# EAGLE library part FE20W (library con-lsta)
FEMALE HEADER
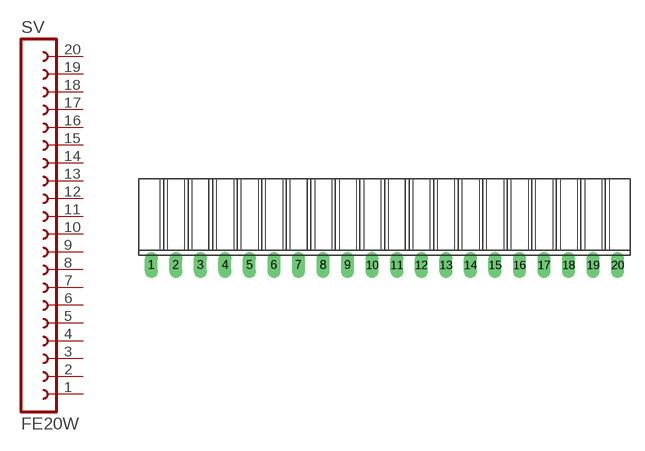
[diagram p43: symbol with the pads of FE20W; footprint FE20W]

Designator prefix SV

## FE20W (OC_FARNELL: unknown; OC_NEWARK: unknown)  [FE20W]
1  1  pas
2  2  pas
3  3  pas
4  4  pas
5  5  pas
6  6  pas
7  7  pas
8  8  pas
9  9  pas
10  10  pas
11  11  pas
12  12  pas
13  13  pas
14  14  pas
15  15  pas
16  16  pas
17  17  pas
18  18  pas
19  19  pas
20  20  pas

## Footprint FE20W (pad centres in mm)
FEMALE HEADER
drill 0.813 long: 1 -24.13,0; 2 -21.59,0; 3 -19.05,0; 4 -16.51,0; 5 -13.97,0; 6 -11.43,0; 7 -8.89,0; 8 -6.35,0; 9 -3.81,0; 10 -1.27,0; 11 1.27,0; 12 3.81,0; 13 6.35,0; 14 8.89,0; 15 11.43,0; 16 13.97,0; 17 16.51,0; 18 19.05,0; 19 21.59,0; 20 24.13,0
